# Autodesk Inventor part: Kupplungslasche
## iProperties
Author: Administrator
Shininess: 20.0
Angle Display Precision: 2
Document Length Units: 11269
Document Angle Units: 11283
Document Time Units: 11279
Document Mass Units: 11290
Document Length Units Precision: 3
Document Angle Units Precision: 2
Compacted: False
PropertySet Name: _Private Model Information
Created: 2003-04
Part Number: Kupplungslasche
Material: Messing
Document SubType Name: Blech
Designer: Administrator
Control State: 0
Master: False
Checked Out: False
PropertySet Name: Design Tracking Control
Density: 0.0
Volumn: 0.0
Area: 0.0
PropertySet Name: Model Information
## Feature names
1. Biegung2
2. Biegung4
3. Bohrung1 [Hole]
4. Platte1
5. Platte2
6. Biegung1
7. Platte3
8. Biegung3
9. ExtrusionAbwicklung1
